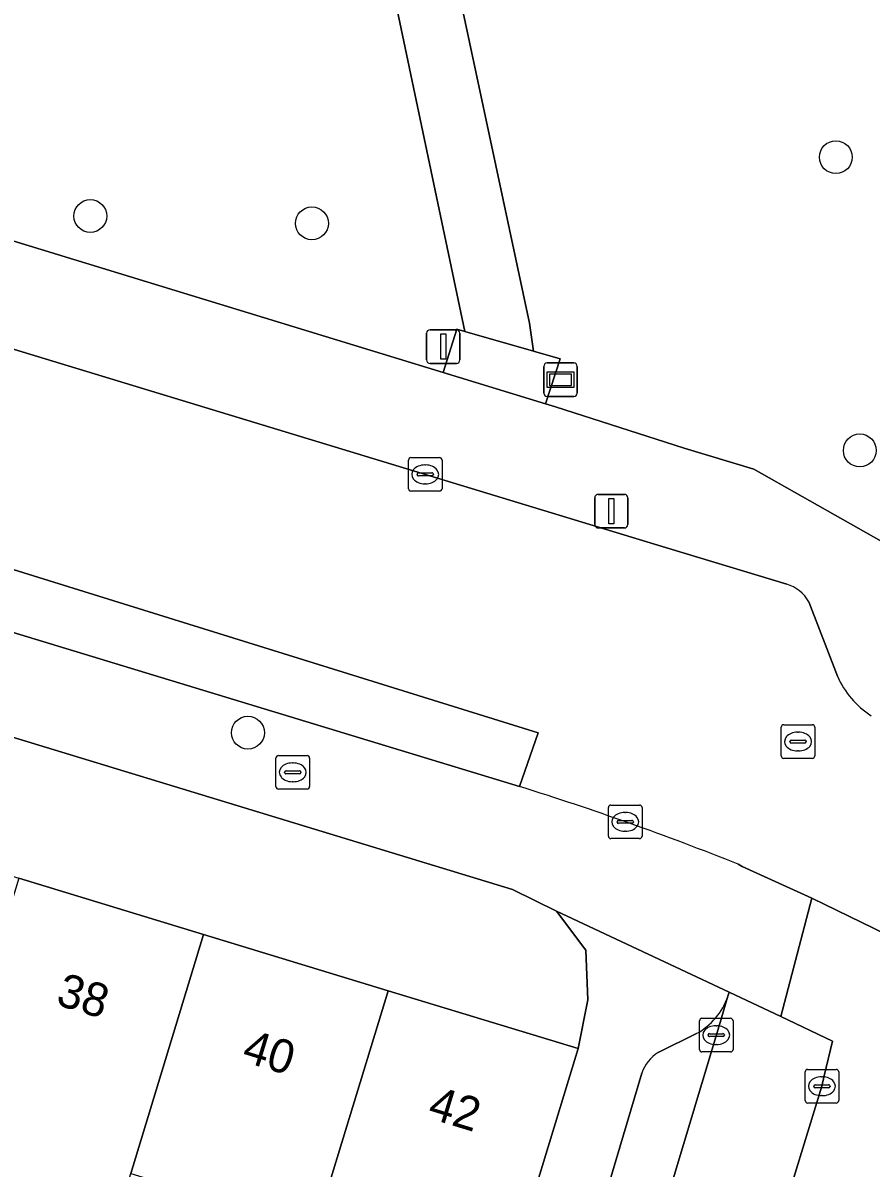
# Model space of a CAD drawing. Extents: x 159817 to 160765, y 380688 to 381638.
# Drawn here: x 160177.54 to 160202.81, y 381036.92 to 381071.03 of the extents above; entities that cross this region are included whole.
import ezdxf

# ---------------------------------------------------------------- set-up
doc = ezdxf.new("R2010")
doc.units = 0
for name, color, linetype in [('IMGEO_Boom', 7, 'Continuous'), ('IMGEO_Brandkraan', 7, 'Continuous'), ('IMGEO_Erf', 7, 'Continuous'), ('IMGEO_Groenvoorziening', 7, 'Continuous'), ('IMGEO_Informatiebord', 7, 'Continuous'), ('IMGEO_Kolk', 7, 'Continuous'), ('IMGEO_Lichtmast', 7, 'Continuous'), ('IMGEO_Pand', 7, 'Continuous'), ('IMGEO_Pand_nummerreeks', 7, 'Continuous'), ('IMGEO_Parkeervlak_open', 7, 'Continuous'), ('IMGEO_Rijbaan_lokaal_open', 7, 'Continuous'), ('IMGEO_Rioolput', 7, 'Continuous'), ('IMGEO_Terreindeel_open', 7, 'Continuous'), ('IMGEO_Verkeersbordpaal', 7, 'Continuous'), ('IMGEO_Voetpad_gesloten', 7, 'Continuous'), ('IMGEO_Voetpad_open', 7, 'Continuous')]:
    doc.layers.add(name, color=color, linetype=linetype)

msp = doc.modelspace()

# ---------------------------------------------------------------- linework, layer by layer
at = {"layer": 'IMGEO_Boom'}
for centre in [(160201.76, 381067.028), (160179.553, 381065.275), (160186.154, 381065.057), (160202.473, 381058.296), (160184.248, 381049.889)]:
    msp.add_circle(centre, 0.489, dxfattribs=at)
at = {"layer": 'IMGEO_Brandkraan'}
for p, q in [((160185.157, 381049.209), (160186.009, 381049.209)), ((160185.082, 381048.283), (160185.082, 381049.135)), ((160185.57, 381048.989), (160185.595, 381048.989)), ((160186.083, 381049.135), (160186.083, 381048.283)), ((160185.341, 381048.703), (160185.341, 381048.715)), ((160185.779, 381048.666), (160185.381, 381048.666)), ((160185.384, 381048.752), (160185.782, 381048.752)), ((160185.825, 381048.715), (160185.825, 381048.703)), ((160186.009, 381048.209), (160185.157, 381048.209)), ((160185.593, 381048.429), (160185.568, 381048.429))]:
    msp.add_line(p, q, dxfattribs=at)
for points in [[(160185.157, 381049.209), (160186.009, 381049.209)], [(160185.082, 381048.283), (160185.082, 381049.135)], [(160186.083, 381049.135), (160186.083, 381048.283)], [(160186.009, 381048.209), (160185.157, 381048.209)]]:
    msp.add_lwpolyline(points, dxfattribs=at)
for centre, radius, start, end in [((160185.159, 381049.133), 0.0765, 91.552, 178.448), ((160185.159, 381049.133), 0.0765, 91.552, 178.448), ((160186.007, 381049.133), 0.0765, 1.552, 88.448), ((160186.007, 381049.133), 0.0765, 1.552, 88.448), ((160185.381, 381048.712), 0.0403, 85.8775, 175.7526), ((160185.378, 381048.702), 0.0366, 178.938, 274.7102), ((160185.782, 381048.709), 0.043, 264.8664, 352.4533), ((160185.786, 381048.714), 0.0386, 1.7309, 96.639), ((160185.159, 381048.285), 0.0765, 181.552, 268.448), ((160185.159, 381048.285), 0.0765, 181.552, 268.448), ((160186.007, 381048.285), 0.0765, 271.552, 358.448), ((160186.007, 381048.285), 0.0765, 271.552, 358.448)]:
    msp.add_arc(centre, radius, start, end, dxfattribs=at)
for centre, major_axis, ratio, start_param, end_param in [((160185.569, 381048.709), (-0.387, 0.002), 0.722429, 4.712389, 7.853982), ((160185.594, 381048.709), (-0.39, 0.002), 0.717154, 1.570796, 4.712389)]:
    msp.add_ellipse(centre, major_axis=major_axis, ratio=ratio, start_param=start_param, end_param=end_param, dxfattribs=at)
at = {"layer": 'IMGEO_Erf'}
msp.add_lwpolyline([(160155.42, 381052.254), (160160.92, 381050.579), (160166.421, 381048.904), (160171.922, 381047.229), (160177.422, 381045.555), (160182.923, 381043.88), (160188.424, 381042.205), (160194.082, 381040.482), (160194.368, 381041.932), (160194.318, 381043.409), (160193.44, 381044.574), (160192.132, 381045.221), (160150.121, 381058.011)], dxfattribs=at)
at = {"layer": 'IMGEO_Groenvoorziening'}
msp.add_lwpolyline([(160187.866, 381084.407), (160192.634, 381062.086), (160192.758, 381061.248), (160193.546, 381061.02), (160193.111, 381059.684), (160193.405, 381059.59), (160197.247, 381058.362), (160199.314, 381057.74), (160206.52, 381053.665), (160209.819, 381051.8), (160210.717, 381051.603), (160210.881, 381051.599)], dxfattribs=at)
msp.add_lwpolyline([(160152.489, 381072.123), (160153.769, 381071.728), (160190.068, 381060.613), (160190.47, 381061.909), (160190.705, 381061.841), (160188.051, 381074.489), (160167.111, 381073.51), (160163.493, 381083.612), (160152.583, 381081.495), (160151.707, 381081.325)], close=True, dxfattribs=at)
at = {"layer": 'IMGEO_Informatiebord'}
for p, q in [((160193.065, 381059.999), (160193.065, 381060.799)), ((160193.065, 381060.799), (160193.065, 381059.999)), ((160193.165, 381060.899), (160193.955, 381060.899)), ((160193.955, 381060.899), (160193.165, 381060.899)), ((160194.055, 381060.799), (160194.055, 381059.999)), ((160194.055, 381059.999), (160194.055, 381060.799)), ((160193.955, 381059.899), (160193.165, 381059.899)), ((160193.165, 381059.899), (160193.955, 381059.899))]:
    msp.add_line(p, q, dxfattribs=at)
for points in [[(160193.166, 381060.631), (160193.954, 381060.631), (160193.954, 381060.167), (160193.166, 381060.167), (160193.166, 381060.631)], [(160193.231, 381060.566), (160193.231, 381060.232), (160193.889, 381060.232), (160193.889, 381060.566), (160193.231, 381060.566)]]:
    msp.add_lwpolyline(points, dxfattribs=at)
for centre, start, end in [((160193.165, 381060.799), 90, 180), ((160193.165, 381060.799), 90, 180), ((160193.955, 381060.799), 0, 90), ((160193.955, 381060.799), 360, 90), ((160193.165, 381059.999), 180, 270), ((160193.165, 381059.999), 180, 270), ((160193.955, 381059.999), 270, 0), ((160193.955, 381059.999), 270, 0)]:
    msp.add_arc(centre, 0.1, start, end, dxfattribs=at)
at = {"layer": 'IMGEO_Kolk'}
for p, q in [((160189.104, 381058.082), (160189.956, 381058.082)), ((160189.029, 381057.156), (160189.029, 381058.008)), ((160189.517, 381057.862), (160189.542, 381057.862)), ((160190.03, 381058.008), (160190.03, 381057.156)), ((160189.288, 381057.576), (160189.288, 381057.588)), ((160189.726, 381057.539), (160189.328, 381057.539)), ((160189.331, 381057.625), (160189.729, 381057.625)), ((160189.772, 381057.588), (160189.772, 381057.576)), ((160189.956, 381057.082), (160189.104, 381057.082)), ((160189.54, 381057.302), (160189.515, 381057.302)), ((160194.986, 381046.808), (160194.986, 381047.66)), ((160195.061, 381047.734), (160195.913, 381047.734)), ((160195.474, 381047.514), (160195.499, 381047.514)), ((160195.987, 381047.66), (160195.987, 381046.808)), ((160195.245, 381047.228), (160195.245, 381047.24)), ((160195.683, 381047.191), (160195.285, 381047.191)), ((160195.288, 381047.277), (160195.686, 381047.277)), ((160195.729, 381047.24), (160195.729, 381047.228)), ((160195.497, 381046.954), (160195.472, 381046.954)), ((160195.913, 381046.734), (160195.061, 381046.734)), ((160197.773, 381041.384), (160198.625, 381041.384)), ((160197.698, 381040.458), (160197.698, 381041.31)), ((160198.186, 381041.164), (160198.211, 381041.164)), ((160198.699, 381041.31), (160198.699, 381040.458)), ((160197.957, 381040.878), (160197.957, 381040.89)), ((160198.395, 381040.841), (160197.997, 381040.841)), ((160198, 381040.927), (160198.398, 381040.927)), ((160198.441, 381040.89), (160198.441, 381040.878)), ((160198.625, 381040.384), (160197.773, 381040.384)), ((160198.209, 381040.604), (160198.184, 381040.604)), ((160200.845, 381038.935), (160200.845, 381039.787)), ((160200.92, 381039.861), (160201.772, 381039.861)), ((160201.333, 381039.641), (160201.358, 381039.641)), ((160201.846, 381039.787), (160201.846, 381038.935)), ((160201.104, 381039.355), (160201.104, 381039.367)), ((160201.542, 381039.318), (160201.144, 381039.318)), ((160201.147, 381039.404), (160201.545, 381039.404)), ((160201.588, 381039.367), (160201.588, 381039.355)), ((160201.356, 381039.081), (160201.331, 381039.081)), ((160201.772, 381038.861), (160200.92, 381038.861))]:
    msp.add_line(p, q, dxfattribs=at)
for points in [[(160189.104, 381058.082), (160189.956, 381058.082)], [(160189.029, 381057.156), (160189.029, 381058.008)], [(160190.03, 381058.008), (160190.03, 381057.156)], [(160189.956, 381057.082), (160189.104, 381057.082)], [(160194.986, 381046.808), (160194.986, 381047.66)], [(160195.061, 381047.734), (160195.913, 381047.734)], [(160195.987, 381047.66), (160195.987, 381046.808)], [(160195.913, 381046.734), (160195.061, 381046.734)], [(160197.773, 381041.384), (160198.625, 381041.384)], [(160197.698, 381040.458), (160197.698, 381041.31)], [(160198.699, 381041.31), (160198.699, 381040.458)], [(160198.625, 381040.384), (160197.773, 381040.384)], [(160200.845, 381038.935), (160200.845, 381039.787)], [(160200.92, 381039.861), (160201.772, 381039.861)], [(160201.846, 381039.787), (160201.846, 381038.935)], [(160201.772, 381038.861), (160200.92, 381038.861)]]:
    msp.add_lwpolyline(points, dxfattribs=at)
for centre, radius, start, end in [((160189.106, 381058.006), 0.0765, 91.552, 178.448), ((160189.106, 381058.006), 0.0765, 91.552, 178.448), ((160189.954, 381058.006), 0.0765, 1.552, 88.448), ((160189.954, 381058.006), 0.0765, 1.552, 88.448), ((160189.328, 381057.585), 0.0403, 85.8775, 175.7526), ((160189.325, 381057.575), 0.0366, 178.938, 274.7102), ((160189.729, 381057.582), 0.043, 264.8664, 352.4533), ((160189.733, 381057.587), 0.0386, 1.7309, 96.639), ((160189.106, 381057.158), 0.0765, 181.552, 268.448), ((160189.106, 381057.158), 0.0765, 181.552, 268.448), ((160189.954, 381057.158), 0.0765, 271.552, 358.448), ((160189.954, 381057.158), 0.0765, 271.552, 358.448), ((160195.063, 381047.658), 0.0765, 91.552, 178.448), ((160195.063, 381047.658), 0.0765, 91.552, 178.448), ((160195.911, 381047.658), 0.0765, 1.552, 88.448), ((160195.911, 381047.658), 0.0765, 1.552, 88.448), ((160195.285, 381047.237), 0.0403, 85.8775, 175.7526), ((160195.282, 381047.227), 0.0366, 178.938, 274.7102), ((160195.686, 381047.234), 0.043, 264.8664, 352.4533), ((160195.69, 381047.239), 0.0386, 1.7309, 96.639), ((160195.063, 381046.81), 0.0765, 181.552, 268.448), ((160195.063, 381046.81), 0.0765, 181.552, 268.448), ((160195.911, 381046.81), 0.0765, 271.552, 358.448), ((160195.911, 381046.81), 0.0765, 271.552, 358.448), ((160197.775, 381041.308), 0.0765, 91.552, 178.448), ((160197.775, 381041.308), 0.0765, 91.552, 178.448), ((160198.623, 381041.308), 0.0765, 1.552, 88.448), ((160198.623, 381041.308), 0.0765, 1.552, 88.448), ((160197.997, 381040.887), 0.0403, 85.8775, 175.7526), ((160197.994, 381040.877), 0.0366, 178.938, 274.7102), ((160198.398, 381040.884), 0.043, 264.8664, 352.4533), ((160198.402, 381040.889), 0.0386, 1.7309, 96.639), ((160197.775, 381040.46), 0.0765, 181.552, 268.448), ((160197.775, 381040.46), 0.0765, 181.552, 268.448), ((160198.623, 381040.46), 0.0765, 271.552, 358.448), ((160198.623, 381040.46), 0.0765, 271.552, 358.448), ((160200.922, 381039.785), 0.0765, 91.552, 178.448), ((160200.922, 381039.785), 0.0765, 91.552, 178.448), ((160201.77, 381039.785), 0.0765, 1.552, 88.448), ((160201.77, 381039.785), 0.0765, 1.552, 88.448), ((160201.144, 381039.364), 0.0403, 85.8775, 175.7526), ((160201.141, 381039.354), 0.0366, 178.938, 274.7102), ((160201.545, 381039.361), 0.043, 264.8664, 352.4533), ((160201.549, 381039.366), 0.0386, 1.7309, 96.639), ((160200.922, 381038.937), 0.0765, 181.552, 268.448), ((160200.922, 381038.937), 0.0765, 181.552, 268.448), ((160201.77, 381038.937), 0.0765, 271.552, 358.448), ((160201.77, 381038.937), 0.0765, 271.552, 358.448)]:
    msp.add_arc(centre, radius, start, end, dxfattribs=at)
for centre, major_axis, ratio, start_param, end_param in [((160189.516, 381057.582), (-0.387, 0.002), 0.722429, 4.712389, 7.853982), ((160189.541, 381057.582), (-0.39, 0.002), 0.717154, 1.570796, 4.712389), ((160195.473, 381047.234), (-0.387, 0.002), 0.722429, 4.712389, 7.853982), ((160195.498, 381047.234), (-0.39, 0.002), 0.717154, 1.570796, 4.712389), ((160198.185, 381040.884), (-0.387, 0.002), 0.722429, 4.712389, 7.853982), ((160198.21, 381040.884), (-0.39, 0.002), 0.717154, 1.570796, 4.712389), ((160201.332, 381039.361), (-0.387, 0.002), 0.722429, 4.712389, 7.853982), ((160201.357, 381039.361), (-0.39, 0.002), 0.717154, 1.570796, 4.712389)]:
    msp.add_ellipse(centre, major_axis=major_axis, ratio=ratio, start_param=start_param, end_param=end_param, dxfattribs=at)
at = {"layer": 'IMGEO_Lichtmast'}
for p, q in [((160194.577, 381056.086), (160194.577, 381056.886)), ((160194.577, 381056.886), (160194.577, 381056.086)), ((160194.677, 381056.986), (160195.467, 381056.986)), ((160195.467, 381056.986), (160194.677, 381056.986)), ((160195.567, 381056.886), (160195.567, 381056.086)), ((160195.567, 381056.086), (160195.567, 381056.886)), ((160195.467, 381055.986), (160194.677, 381055.986)), ((160194.677, 381055.986), (160195.467, 381055.986))]:
    msp.add_line(p, q, dxfattribs=at)
msp.add_lwpolyline([(160194.997, 381056.861), (160195.147, 381056.861), (160195.147, 381056.111), (160194.997, 381056.111), (160194.997, 381056.861)], dxfattribs=at)
for centre, start, end in [((160194.677, 381056.886), 90, 180), ((160194.677, 381056.886), 90, 180), ((160195.467, 381056.886), 0, 90), ((160195.467, 381056.886), 360, 90), ((160194.677, 381056.086), 180, 270), ((160194.677, 381056.086), 180, 270), ((160195.467, 381056.086), 270, 0), ((160195.467, 381056.086), 270, 0)]:
    msp.add_arc(centre, 0.1, start, end, dxfattribs=at)
at = {"layer": 'IMGEO_Pand'}
for points in [[(160177.422, 381045.555), (160175.255, 381038.435), (160174.52, 381036.022), (160180.021, 381034.347), (160180.755, 381036.76), (160182.923, 381043.88)], [(160182.923, 381043.88), (160180.755, 381036.76), (160186.255, 381035.086), (160188.424, 381042.205)], [(160188.424, 381042.205), (160186.255, 381035.086), (160191.914, 381033.363), (160194.082, 381040.482)]]:
    msp.add_lwpolyline(points, close=True, dxfattribs=at)
at = {"layer": 'IMGEO_Parkeervlak_open'}
msp.add_lwpolyline([(160169.234, 381057.245), (160168.695, 381055.471), (160192.333, 381048.288), (160192.892, 381049.888)], close=True, dxfattribs=at)
for points in [[(160184.19, 380966.193), (160190.045, 381000), (160195.228, 381030.303), (160195.647, 381032.379), (160198.283, 381041.159), (160198.547, 381042.039)], [(160197.605, 381040.931), (160196.465, 381040.366)], [(160195.978, 381039.749), (160193.908, 381032.775), (160193.54, 381031.098)]]:
    msp.add_lwpolyline(points, dxfattribs=at)
for centre, radius, start, end in [((160196.68, 381042.671), 1.971, 297.9776, 341.2814), ((160197.142, 381039.331), 1.237, 123.186, 160.2458)]:
    msp.add_arc(centre, radius, start, end, dxfattribs=at)
at = {"layer": 'IMGEO_Rijbaan_lokaal_open'}
for points in [[(160200.296, 381054.308), (160196.359, 381055.505), (160171.044, 381063.201), (160169.234, 381057.245), (160192.892, 381049.888), (160192.333, 381048.288)], [(160201.806, 381051.575), (160200.953, 381053.786)], [(160198.851, 381045.971), (160198.975, 381045.903), (160201.05, 381044.964), (160203.633, 381043.699), (160203.909, 381043.552), (160208.641, 381040.93), (160217.531, 381036.037)], [(160198.927, 381031.496), (160200.397, 381036.285), (160201.341, 381039.361), (160201.415, 381039.67), (160201.664, 381040.703), (160200.125, 381041.435), (160198.585, 381042.167), (160198.547, 381042.039), (160198.283, 381041.159), (160195.647, 381032.379), (160195.228, 381030.303), (160190.045, 381000), (160184.19, 380966.193), (160187.313, 380965.321)]]:
    msp.add_lwpolyline(points, dxfattribs=at)
for centre, radius, start, end in [((160200.023, 381053.29), 1.054, 28.0649, 74.9994), ((160204.35, 381052.716), 2.788, 204.1553, 236.4951), ((160166.266, 380964.631), 87.624, 68.16863, 72.69309)]:
    msp.add_arc(centre, radius, start, end, dxfattribs=at)
at = {"layer": 'IMGEO_Rioolput'}
for p, q in [((160200.133, 381049.199), (160200.133, 381050.051)), ((160200.208, 381050.125), (160201.06, 381050.125)), ((160200.621, 381049.905), (160200.646, 381049.905)), ((160201.134, 381050.051), (160201.134, 381049.199)), ((160200.392, 381049.619), (160200.392, 381049.631)), ((160200.83, 381049.582), (160200.432, 381049.582)), ((160200.435, 381049.668), (160200.833, 381049.668)), ((160200.876, 381049.631), (160200.876, 381049.619)), ((160200.644, 381049.345), (160200.619, 381049.345)), ((160201.06, 381049.125), (160200.208, 381049.125))]:
    msp.add_line(p, q, dxfattribs=at)
for points in [[(160200.133, 381049.199), (160200.133, 381050.051)], [(160200.208, 381050.125), (160201.06, 381050.125)], [(160201.134, 381050.051), (160201.134, 381049.199)], [(160201.06, 381049.125), (160200.208, 381049.125)]]:
    msp.add_lwpolyline(points, dxfattribs=at)
for centre, radius, start, end in [((160200.21, 381050.049), 0.0765, 91.552, 178.448), ((160200.21, 381050.049), 0.0765, 91.552, 178.448), ((160201.058, 381050.049), 0.0765, 1.552, 88.448), ((160201.058, 381050.049), 0.0765, 1.552, 88.448), ((160200.432, 381049.628), 0.0403, 85.8775, 175.7526), ((160200.429, 381049.618), 0.0366, 178.938, 274.7102), ((160200.833, 381049.625), 0.043, 264.8664, 352.4533), ((160200.837, 381049.63), 0.0386, 1.7309, 96.639), ((160200.21, 381049.201), 0.0765, 181.552, 268.448), ((160200.21, 381049.201), 0.0765, 181.552, 268.448), ((160201.058, 381049.201), 0.0765, 271.552, 358.448), ((160201.058, 381049.201), 0.0765, 271.552, 358.448)]:
    msp.add_arc(centre, radius, start, end, dxfattribs=at)
for centre, major_axis, ratio, start_param, end_param in [((160200.62, 381049.625), (-0.387, 0.002), 0.722429, 4.712389, 7.853982), ((160200.645, 381049.625), (-0.39, 0.002), 0.717154, 1.570796, 4.712389)]:
    msp.add_ellipse(centre, major_axis=major_axis, ratio=ratio, start_param=start_param, end_param=end_param, dxfattribs=at)
at = {"layer": 'IMGEO_Terreindeel_open'}
msp.add_lwpolyline([(160193.111, 381059.684), (160193.546, 381061.02), (160192.758, 381061.248), (160190.705, 381061.841), (160190.47, 381061.909), (160190.068, 381060.613)], close=True, dxfattribs=at)
at = {"layer": 'IMGEO_Verkeersbordpaal'}
for p, q in [((160189.672, 381061.888), (160190.462, 381061.888)), ((160190.462, 381061.888), (160189.672, 381061.888)), ((160189.572, 381060.988), (160189.572, 381061.788)), ((160189.572, 381061.788), (160189.572, 381060.988)), ((160190.562, 381061.788), (160190.562, 381060.988)), ((160190.562, 381060.988), (160190.562, 381061.788)), ((160190.462, 381060.888), (160189.672, 381060.888)), ((160189.672, 381060.888), (160190.462, 381060.888))]:
    msp.add_line(p, q, dxfattribs=at)
msp.add_lwpolyline([(160189.992, 381061.763), (160190.142, 381061.763), (160190.142, 381061.013), (160189.992, 381061.013), (160189.992, 381061.763)], dxfattribs=at)
for centre, start, end in [((160189.672, 381061.788), 90, 180), ((160189.672, 381061.788), 90, 180), ((160190.462, 381061.788), 0, 90), ((160190.462, 381061.788), 360, 90), ((160189.672, 381060.988), 180, 270), ((160189.672, 381060.988), 180, 270), ((160190.462, 381060.988), 270, 0), ((160190.462, 381060.988), 270, 0)]:
    msp.add_arc(centre, 0.1, start, end, dxfattribs=at)
at = {"layer": 'IMGEO_Voetpad_gesloten'}
msp.add_lwpolyline([(160185.914, 381083.973), (160186.178, 381083.417), (160188.051, 381074.489), (160190.705, 381061.841), (160192.758, 381061.248), (160192.634, 381062.086), (160187.866, 381084.407)], dxfattribs=at)
at = {"layer": 'IMGEO_Voetpad_open'}
for points in [[(160210.881, 381051.599), (160210.717, 381051.603), (160209.819, 381051.8), (160206.52, 381053.665), (160199.314, 381057.74), (160197.247, 381058.362), (160193.405, 381059.59), (160193.111, 381059.684), (160190.068, 381060.613), (160153.769, 381071.728), (160152.489, 381072.123), (160136.348, 381077.101), (160134.16, 381077.77), (160120.204, 381082.036), (160117.259, 381082.928), (160095.705, 381089.314), (160092.73, 381090.233), (160089.904, 381091.107), (160075.881, 381095.343), (160066.472, 381098.413), (160030.475, 381111.405)], [(160073.93, 381092.725), (160077.136, 381091.759), (160078.974, 381091.206), (160089.161, 381088.138), (160092.763, 381087.03), (160105.655, 381083.08), (160108.334, 381082.266), (160168.403, 381064.004), (160171.044, 381063.201), (160196.359, 381055.505), (160200.296, 381054.308)], [(160143.104, 381060.147), (160150.121, 381058.011), (160192.132, 381045.221), (160193.44, 381044.574), (160198.585, 381042.167), (160200.125, 381041.435), (160201.05, 381044.964), (160198.975, 381045.903), (160198.851, 381045.971)], [(160192.333, 381048.288), (160168.695, 381055.471)], [(160200.953, 381053.786), (160201.806, 381051.575)], [(160217.531, 381036.037), (160208.641, 381040.93), (160203.909, 381043.552), (160203.633, 381043.699), (160201.05, 381044.964), (160200.125, 381041.435), (160201.664, 381040.703), (160201.415, 381039.67), (160201.341, 381039.361), (160200.397, 381036.285), (160203.467, 381035.401), (160225.828, 381029.258), (160227.232, 381028.872), (160273.402, 381016.188), (160276.352, 381015.377), (160309.745, 381006.087), (160312.885, 381005.214), (160331.627, 381000), (160361.208, 380991.958)], [(160198.547, 381042.039), (160198.585, 381042.167), (160193.44, 381044.574), (160194.318, 381043.409), (160194.368, 381041.932), (160194.082, 381040.482), (160191.914, 381033.363), (160190.824, 381026.637), (160189.827, 381020.68), (160189.566, 381019.12), (160186.367, 381000), (160182.732, 380979.036), (160182.303, 380976.564), (160177.667, 380949.826), (160181.361, 380949.186), (160181.713, 380951.257), (160179.939, 380951.559), (160180.697, 380956.015), (160182.47, 380955.713), (160182.727, 380957.221), (160180.953, 380957.523), (160181.707, 380961.96), (160183.481, 380961.658), (160184.19, 380965.829)], [(160196.465, 381040.366), (160197.605, 381040.931)], [(160193.54, 381031.098), (160193.908, 381032.775), (160195.978, 381039.749)]]:
    msp.add_lwpolyline(points, dxfattribs=at)
for centre, radius, start, end in [((160200.023, 381053.29), 1.054, 28.0649, 74.9994), ((160204.35, 381052.716), 2.788, 204.1553, 236.4951), ((160166.266, 380964.631), 87.624, 68.16863, 72.69309), ((160196.68, 381042.671), 1.971, 297.9776, 341.2814), ((160197.142, 381039.331), 1.237, 123.186, 160.2458)]:
    msp.add_arc(centre, radius, start, end, dxfattribs=at)

# ---------------------------------------------------------------- texts
at = {"layer": 'IMGEO_Pand_nummerreeks'}
for s, p in [('38', (160178.491, 381041.8)), ('40', (160184.03, 381040.114)), ('42', (160189.564, 381038.429))]:
    msp.add_text(s, height=1, rotation=343.0656, dxfattribs=at).set_placement(p)

doc.saveas('drawing.dxf')
